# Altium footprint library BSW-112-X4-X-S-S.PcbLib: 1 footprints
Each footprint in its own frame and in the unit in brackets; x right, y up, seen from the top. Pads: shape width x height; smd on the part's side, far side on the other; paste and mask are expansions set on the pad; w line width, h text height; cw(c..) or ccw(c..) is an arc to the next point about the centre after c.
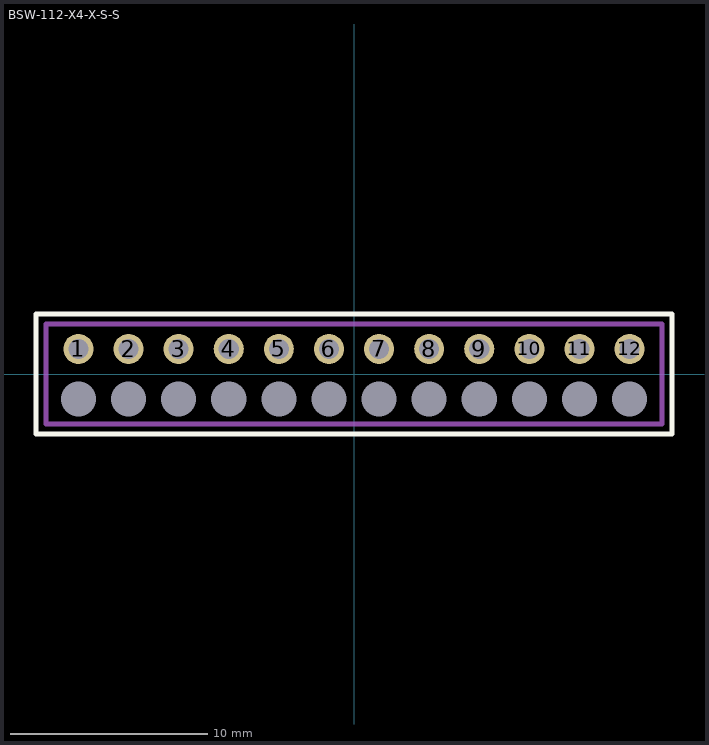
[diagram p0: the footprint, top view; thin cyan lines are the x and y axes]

## BSW-112-X4-X-S-S [mil]
pads (24):
  round 60 hole 40 mask+3: 1(-550,50) 2(-450,50) 3(-350,50) 4(-250,50) 5(-150,50) 6(-50,50) 7(50,50) 8(150,50) 9(250,50) 10(350,50) 11(450,50) 12(550,50)
  round 0 hole 70 unplated: 13(-550,-50) 14(-450,-50) 15(-350,-50) 16(-250,-50) 17(-150,-50) 18(-50,-50) 19(50,-50) 20(150,-50) 21(250,-50) 22(350,-50) 23(450,-50) 24(550,-50)
Top Overlay:
  lines w10: -635,-120 -635,120 635,120 635,-120 -635,-120
Mechanical 1:
  lines w10: -615,-100 -615,100 615,100 615,-100 -615,-100
  text "J1" at -17.57,-18 h30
